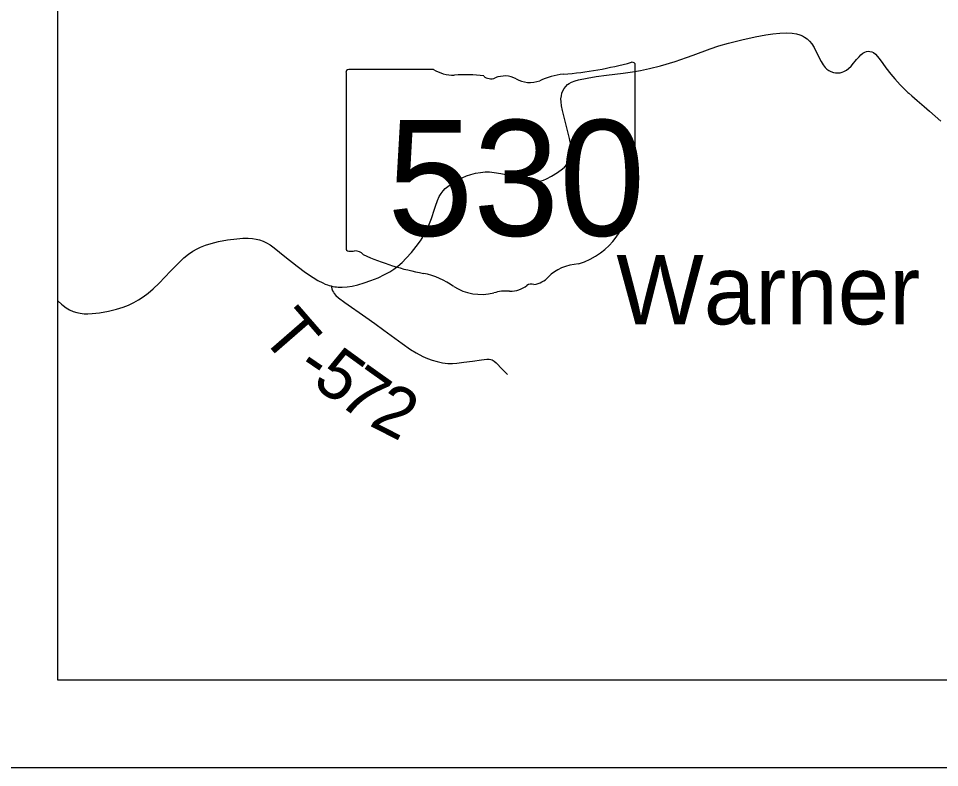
# Model space of a CAD drawing. Extents: x 0 to 34, y 0 to 22.
# Drawn here: x 2.055 to 3.105, y 14 to 14.853 of the extents above; entities that cross this region are included whole.
import ezdxf

# ---------------------------------------------------------------- set-up
doc = ezdxf.new("R2010")
doc.units = 0
for name, color, linetype in [('GM_X_Corporation', 7, 'Continuous'), ('GM_X_State_Route', 7, 'Continuous'), ('GM_X_State_Shield', 7, 'Continuous'), ('GM_X_Township_Road', 7, 'Continuous'), ('GM_X_Township_Road_Text', 7, 'Continuous'), ('GM_X_Unincorporated_Text', 7, 'Continuous'), ('SH_Data', 7, 'Continuous'), ('SH_Text', 7, 'Continuous')]:
    doc.layers.add(name, color=color, linetype=linetype)

msp = doc.modelspace()

# ---------------------------------------------------------------- linework, layer by layer
at = {"layer": 'GM_X_Corporation'}
msp.add_lwpolyline([(2.1, 19.4241), (2.1, 14.1), (8.9, 14.1), (8.9, 16.8499)], dxfattribs=at)
at = {"layer": 'GM_X_State_Route'}
msp.add_lwpolyline([(2.1, 14.5319), (2.1006, 14.5312), (2.1043, 14.5278), (2.1062, 14.5262), (2.1098, 14.5236), (2.1136, 14.5214), (2.1177, 14.5195), (2.1219, 14.5182), (2.1257, 14.5175), (2.1301, 14.517), (2.1345, 14.517), (2.1395, 14.5173), (2.1476, 14.518), (2.158, 14.5199), (2.1671, 14.5222), (2.1748, 14.5246), (2.1807, 14.5269), (2.187, 14.5298), (2.1924, 14.5329), (2.1977, 14.5363), (2.2032, 14.5405), (2.2088, 14.5454), (2.2156, 14.5519), (2.2286, 14.5653), (2.2381, 14.575), (2.244, 14.5805), (2.2492, 14.5848), (2.2542, 14.5883), (2.259, 14.591), (2.2629, 14.5929), (2.2686, 14.5951), (2.2751, 14.5971), (2.2835, 14.5991), (2.2938, 14.601), (2.3042, 14.6024), (2.311, 14.603), (2.3171, 14.6031), (2.322, 14.6028), (2.3262, 14.6021), (2.3303, 14.6011), (2.3343, 14.5996), (2.3381, 14.5978), (2.3423, 14.5953), (2.3468, 14.592), (2.3589, 14.5823), (2.373, 14.5711), (2.3825, 14.5641), (2.3913, 14.5581), (2.3967, 14.5549), (2.4023, 14.552), (2.4049, 14.5508), (2.4075, 14.5499), (2.4096, 14.5491), (2.4118, 14.5486), (2.4138, 14.5481), (2.416, 14.5477), (2.4178, 14.5475), (2.4199, 14.5473), (2.4243, 14.5473), (2.43, 14.5477), (2.4356, 14.5485), (2.4423, 14.5499), (2.4495, 14.552), (2.4572, 14.5547), (2.4653, 14.558), (2.4727, 14.5615), (2.4787, 14.5648), (2.4834, 14.5679), (2.4879, 14.5713), (2.4926, 14.5755), (2.4975, 14.5803), (2.5034, 14.5868), (2.5089, 14.5936), (2.5137, 14.6002), (2.5174, 14.606), (2.5207, 14.612), (2.5233, 14.6177), (2.5262, 14.6254), (2.5296, 14.6361), (2.5307, 14.6396), (2.533, 14.646), (2.535, 14.6504), (2.5372, 14.654), (2.5394, 14.6569), (2.5419, 14.6595), (2.5447, 14.6619), (2.5487, 14.6647), (2.555, 14.6685), (2.561, 14.6717), (2.566, 14.6739), (2.5712, 14.6757), (2.5765, 14.6771), (2.582, 14.678), (2.5875, 14.6785), (2.5923, 14.6785), (2.5978, 14.678), (2.6051, 14.6769), (2.6129, 14.6751), (2.6321, 14.6698), (2.6388, 14.6682), (2.6438, 14.6677), (2.6476, 14.6679), (2.6508, 14.6684), (2.6539, 14.6692), (2.6574, 14.6706), (2.663, 14.6736), (2.6698, 14.678), (2.6755, 14.682), (2.6779, 14.6841), (2.6805, 14.6869), (2.6821, 14.6896), (2.6832, 14.6912), (2.6843, 14.6942), (2.685, 14.6961), (2.6851, 14.6967), (2.6855, 14.7005), (2.6855, 14.7037), (2.6849, 14.7093), (2.6835, 14.7167), (2.6798, 14.7318), (2.6756, 14.7486), (2.6744, 14.754), (2.6739, 14.7582), (2.6738, 14.7618), (2.6742, 14.7654), (2.6749, 14.7683), (2.6759, 14.771), (2.6774, 14.7736), (2.6792, 14.776), (2.6814, 14.778), (2.6832, 14.7794), (2.6859, 14.7808), (2.6898, 14.7824), (2.6939, 14.7835), (2.7036, 14.7853), (2.714, 14.7873), (2.7256, 14.7889), (2.7447, 14.791), (2.7552, 14.7924), (2.7644, 14.7939), (2.7748, 14.7962), (2.7874, 14.7995), (2.8041, 14.8044), (2.817, 14.8088), (2.8246, 14.8116), (2.8437, 14.8189), (2.8536, 14.8222), (2.8649, 14.8254), (2.8799, 14.8292), (2.895, 14.8326), (2.9072, 14.8349), (2.9151, 14.836), (2.9231, 14.8367), (2.9312, 14.8369), (2.9373, 14.8366), (2.9421, 14.8359), (2.9462, 14.8348), (2.9489, 14.8337), (2.9515, 14.8322), (2.9544, 14.8301), (2.957, 14.8276), (2.9596, 14.8243), (2.9622, 14.8201), (2.9659, 14.813), (2.9705, 14.8042), (2.9727, 14.8004), (2.9751, 14.7974), (2.9769, 14.7957), (2.979, 14.7941), (2.9813, 14.7929), (2.9843, 14.7919), (2.9868, 14.7914), (2.9894, 14.7913), (2.992, 14.7916), (2.9944, 14.7923), (2.9962, 14.793), (2.9991, 14.7946), (3.0017, 14.7965), (3.0045, 14.799), (3.0074, 14.8023), (3.0093, 14.8046), (3.0108, 14.8065), (3.0135, 14.8098), (3.0156, 14.8119), (3.0179, 14.8137), (3.02, 14.8148), (3.0222, 14.8156), (3.0244, 14.816), (3.026, 14.8159), (3.028, 14.8154), (3.0299, 14.8144), (3.0322, 14.8127), (3.0346, 14.8102), (3.0376, 14.8064), (3.0408, 14.8019), (3.0441, 14.7973), (3.0497, 14.7898), (3.0542, 14.7846), (3.0605, 14.7777), (3.0631, 14.7751), (3.0693, 14.7691), (3.0701, 14.7683), (3.0736, 14.7651), (3.0797, 14.7599), (3.0877, 14.753), (3.0938, 14.7478), (3.1068, 14.7364)], dxfattribs=at)
at = {"layer": 'GM_X_State_Shield'}
for p, q in [((2.5285, 14.7952), (2.432, 14.7952)), ((2.7583, 14.6955), (2.7583, 14.8002)), ((2.4288, 14.7918), (2.4288, 14.5916)), ((2.7583, 14.6955), (2.7583, 14.6955))]:
    msp.add_line(p, q, dxfattribs=at)
for centre, major_axis, start_param, end_param in [((2.4325, 14.7922), (0.00382, 0), 1.712693, 3.28349), ((2.5515, 14.8184), (0.037, 0), 4.042523, 4.731795), ((2.6409, 15.068), (0.3495, 0), 4.814394, 5.042369), ((2.7547, 14.8006), (0.00367, 0), 6.141152, 7.989035), ((2.5638, 14.6829), (0.133, 0), 1.404758, 1.657858), ((2.594, 14.7932), (0.0107, 0), 3.836095, 5.185415), ((2.6097, 14.7701), (0.0222, 0), 0.950623, 2.079405), ((2.6383, 14.8018), (0.0267, 0), 4.081561, 5.145723), ((2.6855, 14.7341), (0.0703, 0), 1.699011, 2.107814), ((2.7575, 14.6878), (0.00568, 0), 1.883978, 3.671073), ((2.7544, 14.6951), (0.00393, 0), 5.05454, 6.418171), ((2.7214, 14.6746), (0.0341, 0), 5.934695, 6.695948), ((2.7715, 14.6517), (0.0248, 0), 2.387724, 3.262537), ((2.6605, 14.6384), (0.0874, 0), 5.101752, 6.440018), ((2.4326, 14.5912), (0.00385, 0), 3.00124, 4.508301), ((2.4332, 14.6117), (0.0294, 0), 4.665946, 4.897461), ((2.4392, 14.5801), (0.0106, 0), 0.519207, 1.627899), ((2.573, 14.7599), (0.2524, 0), 4.195997, 4.488961), ((2.6974, 14.5355), (0.0479, 0), 1.647645, 2.488434), ((2.4977, 14.5017), (0.079, 0), 0.823519, 1.323587), ((2.6367, 14.5722), (0.0282, 0), 4.937069, 5.64225), ((2.5832, 14.5791), (0.0501, 0), 4.026481, 4.996735), ((2.6121, 14.5099), (0.0412, 0), 1.495662, 1.94098), ((2.6158, 14.5641), (0.0267, 0), 4.691044, 5.507374), ((2.6399, 14.5447), (0.00752, 0), 1.147584, 2.315152)]:
    msp.add_ellipse(centre, major_axis=major_axis, ratio=0.8, start_param=start_param, end_param=end_param, dxfattribs=at)
at = {"layer": 'GM_X_Township_Road'}
msp.add_lwpolyline([(2.4118, 14.5486), (2.4127, 14.5455), (2.4135, 14.543), (2.4143, 14.5415), (2.4152, 14.54), (2.4172, 14.5376), (2.42, 14.5351), (2.4275, 14.5296), (2.4515, 14.5129), (2.4616, 14.5057), (2.4717, 14.4984), (2.4926, 14.4829), (2.5023, 14.4761), (2.5087, 14.4723), (2.5164, 14.4682), (2.5215, 14.4659), (2.5268, 14.464), (2.5328, 14.4624), (2.5389, 14.4612), (2.545, 14.4604), (2.55, 14.4603), (2.5549, 14.4606), (2.5629, 14.4617), (2.5728, 14.4631), (2.5833, 14.4644), (2.5892, 14.4651), (2.5919, 14.4653), (2.5937, 14.465), (2.5955, 14.4643), (2.5976, 14.4631), (2.6, 14.4611), (2.6069, 14.4539), (2.6112, 14.4494), (2.613, 14.4477)], dxfattribs=at)
at = {"layer": 'SH_Data'}
for p, q in [((2.1, 20.9), (2.1, 14.1)), ((2.1, 14.1), (8.9, 14.1)), ((2.1, 14.1), (2.1, 14.1)), ((2, 14), (9, 14))]:
    msp.add_line(p, q, dxfattribs=at)
at = {"layer": 'SH_Text'}
msp.add_lwpolyline([(2.1, 16.074), (2.1, 14.1), (6.4323, 14.1)], dxfattribs=at)

# ---------------------------------------------------------------- texts
at = {"layer": 'GM_X_State_Shield'}
msp.add_text('530', height=0.13184, dxfattribs=at).set_placement((2.4757, 14.6058))
at = {"layer": 'GM_X_Township_Road_Text'}
for s, rotation, p in [('T', 310.9876, (2.33, 14.4919)), ('5', 323.9263, (2.3886, 14.4364)), ('-', 325.7054, (2.3697, 14.4492)), ('7', 324.5879, (2.4175, 14.4153)), ('2', 332.9562, (2.4537, 14.3904))]:
    msp.add_text(s, height=0.0568, rotation=rotation, dxfattribs=at).set_placement(p)
at = {"layer": 'GM_X_Unincorporated_Text'}
msp.add_text('Warner', height=0.07898, rotation=0, dxfattribs=at).set_placement((2.7369, 14.5049))

doc.saveas('drawing.dxf')
